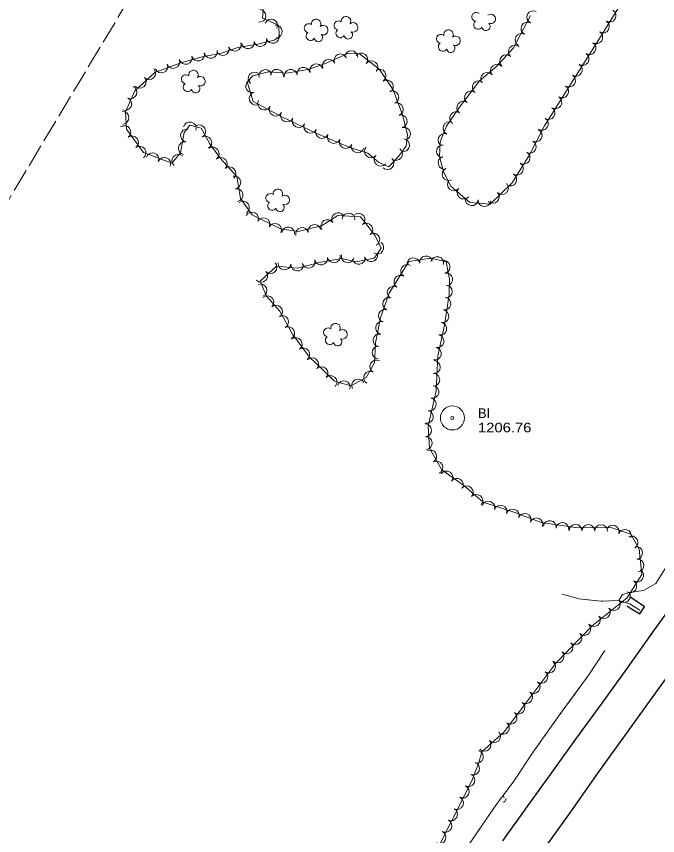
# Model space of a CAD drawing. Extents: x 298761 to 300931, y 48584 to 50968.
# Drawn here: x 299612 to 300012, y 49634 to 50145 of the extents above; entities that cross this region are included whole.
import ezdxf

# ---------------------------------------------------------------- set-up
doc = ezdxf.new("R2010")
doc.units = 0
doc.header["$LTSCALE"] = 2.4
doc.linetypes.add('LONG_DASHED', pattern=[7.5, 6, -1.5])
for name, color, linetype, lineweight in [('11', 7, 'Continuous', 25), ('15', 7, 'Continuous', 13), ('18', 7, 'Continuous', 13), ('19', 7, 'Continuous', 13), ('4', 7, 'Continuous', 13), ('6', 7, 'Continuous', 13)]:
    doc.layers.add(name, color=color, linetype=linetype, lineweight=lineweight)

msp = doc.modelspace()

# ---------------------------------------------------------------- linework, layer by layer
at = {"layer": '11'}
for points in [[(299915.873, 49630.321), (299931.973, 49652.924), (299946.639, 49673.137), (299961.48, 49693.774), (299977.848, 49716.32), (299993.395, 49737.881), (300010.454, 49762.179), (300027.109, 49784.923), (300040.39, 49803.549), (300059.076, 49829.713), (300075.951, 49853.169), (300090.619, 49873.467), (300108.059, 49897.84), (300124.331, 49920.482), (300138.8, 49940.607), (300155.789, 49964.508), (300172.496, 49987.622), (300191.823, 50014.425), (300209.423, 50038.876), (300227.388, 50064), (300243.582, 50086.409), (300257.176, 50105.425), (300269.259, 50122.088)], [(299941.753, 49625.456), (299958.193, 49648.483), (299975.851, 49673.327), (299990.952, 49694.469), (300010.158, 49721.046), (300026.858, 49744.237), (300044.29, 49768.502), (300061.337, 49792.04), (300080.812, 49818.961), (300101.569, 49847.571), (300120.862, 49874.589), (300136.668, 49896.558), (300155.344, 49923.099), (300176.493, 49952.718), (300194.769, 49978.148), (300214.8, 50006.036), (300236.015, 50035.498), (300257.333, 50065.558), (300273.546, 50088.222), (300287.176, 50107.164)]]:
    msp.add_lwpolyline(points, dxfattribs=at)
at = {"layer": '15', "lineweight": 25}
msp.add_lwpolyline([(299993.22, 49777.093), (299995.217, 49775.769), (300001.302, 49772.039), (300004.276, 49776.384), (299998.285, 49780.558), (299995.294, 49782.557)], dxfattribs=at)
at = {"layer": '15'}
msp.add_arc((299915.879, 49656.261), 1.814, 267.88039, 14.11996, dxfattribs=at)
at = {"layer": '18'}
for points in [[(299933.049, 50145.973), (299922.588, 50125.718), (299912.11, 50114.179), (299901.213, 50105.093), (299888.085, 50087.85), (299880.698, 50076.691), (299876.582, 50066.912), (299876.181, 50057.745), (299878.849, 50048.238), (299883.29, 50039.31), (299895.277, 50029.09), (299907.913, 50028.131), (299921.747, 50041.406), (299932.377, 50058.937), (299941.814, 50076.925), (299960.207, 50106.094), (299976.815, 50132.544), (299999.456, 50169.437)], [(299876.275, 49627.887), (299891.116, 49656.997), (299896.966, 49668.752), (299900.82, 49679.139), (299902.684, 49685.849), (299916.63, 49698.459), (299933.285, 49720.361), (299948.899, 49741.267), (299971.578, 49764.647), (299984.015, 49774.503), (299993.254, 49781.947), (300002.651, 49796.774), (300000.918, 49812.588), (299995.831, 49821.813), (299983.919, 49825.836), (299961.184, 49826.042), (299939.705, 49829.183), (299923.913, 49835.134), (299903.509, 49841.801), (299891.565, 49852.222), (299877.646, 49861.998), (299869.95, 49875.684), (299869.244, 49889.438), (299874.196, 49911.402), (299875.17, 49933.356), (299879.366, 49952.538), (299882.29, 49971.577), (299882.575, 49981.193), (299880.385, 49992.018), (299870.949, 49994.324), (299857.19, 49992.154), (299844.909, 49972.449), (299839.431, 49957.01), (299836.315, 49941.374), (299835.746, 49929.004), (299830.565, 49919.818), (299820.828, 49914.584), (299810.698, 49917.533), (299802.151, 49925.827), (299795.085, 49932.492), (299784.539, 49946.75), (299776.599, 49961.272), (299768.268, 49970.524), (299764.357, 49979.899), (299774.434, 49989.353), (299787.655, 49988.159), (299802.096, 49991.862), (299815.183, 49994.133), (299824.307, 49991.981), (299835.486, 49994.317), (299839.757, 50000.568), (299836.109, 50008.351), (299830.568, 50015.668), (299826.963, 50020.166), (299812.741, 50021.043), (299802.558, 50014.574), (299788.088, 50010.998), (299777.048, 50012.592), (299759.232, 50021.403), (299751.972, 50031.678), (299749.613, 50045.385), (299739.553, 50056.478), (299732.832, 50065.661), (299727.505, 50075.492), (299720.386, 50077.486), (299716.719, 50072.761), (299714.489, 50060.051), (299709.158, 50053.718), (299691.46, 50060.346), (299680.801, 50074.84), (299680.15, 50085.825), (299685.979, 50098.782), (299698.448, 50110.252), (299714.75, 50116.42), (299728.009, 50120.006), (299740.145, 50122.434), (299750.282, 50126.002), (299762.861, 50128.024), (299772.978, 50130.55), (299776.438, 50132.498), (299775.707, 50139.951), (299765.739, 50144.23), (299766.764, 50155.882)]]:
    msp.add_lwpolyline(points, dxfattribs=at)
msp.add_lwpolyline([(299847.305, 50099.383), (299838.874, 50112.086), (299831.645, 50117.807), (299826.357, 50121.902), (299818.74, 50122.079), (299812.492, 50119.322), (299804.54, 50115.619), (299794.093, 50112.158), (299780.681, 50109.864), (299769.487, 50110.804), (299759.586, 50108.305), (299756.232, 50104.469), (299759.795, 50092.252), (299777.882, 50082.645), (299799.618, 50072.247), (299820.276, 50063.532), (299831.5, 50059.942), (299838.32, 50054.077), (299844.523, 50051.411), (299850.415, 50057.694), (299855.549, 50064.338), (299856.369, 50071.605), (299853.147, 50083.876)], close=True, dxfattribs=at)
for centre, radius, start, end in [((299763.766, 50145.667), 3.995, 264.98042, 84.9651), ((299934.844, 50144.892), 3.995, 62.69289, 242.67757), ((299982.54, 50145.87), 3.995, 238.47049, 58.45516), ((299771.099, 50139.653), 3.995, 336.77509, 156.75977), ((299799.268, 50140.673), 2.974, 328.01895, 189.25284), ((299817.879, 50142.36), 2.974, 328.01895, 189.25284), ((299899.23, 50145.045), 2.777, 50.98984, 258.76284), ((299908.298, 50143.803), 2.975, 245.66977, 128.64304), ((299774.004, 50135.893), 3.995, 275.60939, 95.59407), ((299794.585, 50138.037), 2.777, 50.98984, 258.76284), ((299803.653, 50136.795), 2.975, 245.66977, 128.64304), ((299813.196, 50139.724), 2.777, 50.98984, 258.76284), ((299822.264, 50138.482), 2.975, 245.66977, 128.64304), ((299900.39, 50140.119), 2.783, 127.66686, 328.6779), ((299905.336, 50139.142), 2.611, 190.375, 48.30761), ((299931.178, 50137.794), 3.995, 62.69289, 242.67757), ((299978.361, 50139.061), 3.995, 238.47049, 58.45516), ((299772.081, 50132.481), 3.995, 194.02658, 14.01126), ((299795.745, 50133.111), 2.783, 127.66686, 328.6779), ((299800.691, 50132.134), 2.611, 190.375, 48.30761), ((299814.356, 50134.798), 2.783, 127.66686, 328.6779), ((299819.302, 50133.821), 2.611, 190.375, 48.30761), ((299877.177, 50131.349), 2.777, 50.98984, 258.76284), ((299881.86, 50133.985), 2.974, 328.01895, 189.25284), ((299886.245, 50130.107), 2.975, 245.66977, 128.64304), ((299927.512, 50130.695), 3.995, 62.69289, 242.67757), ((299974.179, 50132.279), 3.995, 237.88288, 57.86756), ((299748.454, 50127.575), 3.995, 199.3986, 19.38328), ((299756.651, 50129.144), 3.995, 189.1395, 9.12418), ((299764.33, 50130.546), 3.995, 194.02658, 14.01126), ((299878.337, 50126.423), 2.783, 127.66686, 328.6779), ((299969.931, 50125.513), 3.995, 237.88288, 57.86756), ((299733.426, 50123.222), 3.995, 191.32122, 11.3059), ((299740.918, 50124.923), 3.995, 199.3986, 19.38328), ((299821.14, 50119.91), 4.036, 358.67649, 178.66117), ((299883.283, 50125.446), 2.611, 190.375, 48.30761), ((299923.257, 50123.344), 3.995, 47.76661, 227.75129), ((299709.998, 50116.858), 3.995, 200.73222, 20.7169), ((299717.775, 50119.404), 3.995, 195.14168, 15.12636), ((299725.488, 50121.49), 3.995, 195.14168, 15.12636), ((299807.162, 50114.509), 4.036, 24.9776, 204.96228), ((299814.45, 50117.877), 4.036, 23.81767, 203.80235), ((299827.358, 50118.455), 4.036, 322.25364, 142.23832), ((299917.886, 50117.43), 3.995, 47.76661, 227.75129), ((299965.683, 50118.747), 3.995, 237.88288, 57.86756), ((299694.944, 50109.869), 3.995, 222.61803, 42.60271), ((299702.526, 50114.031), 3.995, 200.73222, 20.7169), ((299791.266, 50109.531), 4.036, 9.71366, 189.69834), ((299799.354, 50111.675), 4.036, 18.33724, 198.32192), ((299833.695, 50113.491), 4.036, 321.64972, 141.6344), ((299912.144, 50111.485), 3.995, 39.82926, 219.81394), ((299961.434, 50111.981), 3.995, 237.88288, 57.86756), ((299717.87, 50106.128), 2.777, 50.98984, 258.76284), ((299722.553, 50108.764), 2.974, 328.01895, 189.25284), ((299726.938, 50104.886), 2.975, 245.66977, 128.64304), ((299760.871, 50106.565), 4.036, 48.84289, 228.82757), ((299767.479, 50108.118), 4.036, 14.17319, 194.15786), ((299774.759, 50108.241), 4.036, 355.20759, 175.19227), ((299783.31, 50108.17), 4.036, 9.71366, 189.69834), ((299838.849, 50108.303), 4.036, 303.57995, 123.56463), ((299906.008, 50106.368), 3.995, 39.82926, 219.81394), ((299957.184, 50105.221), 3.995, 237.7735, 57.75818), ((299689.064, 50104.461), 3.995, 222.61803, 42.60271), ((299719.03, 50101.202), 2.783, 127.66686, 328.6779), ((299759.223, 50101.758), 4.036, 106.26661, 286.25128), ((299843.313, 50101.578), 4.036, 303.57995, 123.56463), ((299900.763, 50101.05), 3.995, 52.72374, 232.70842), ((299683.303, 50097.93), 3.995, 245.78598, 65.77066), ((299723.976, 50100.225), 2.611, 190.375, 48.30761), ((299761.483, 50094.009), 4.036, 106.26661, 286.25128), ((299846.751, 50094.862), 4.036, 290.65071, 110.63539), ((299895.923, 50094.693), 3.995, 52.72374, 232.70842), ((299952.923, 50098.463), 3.995, 237.7735, 57.75818), ((299680.025, 50090.645), 3.995, 245.78598, 65.77066), ((299766.842, 50090.901), 4.036, 152.03243, 332.01711), ((299891.083, 50088.336), 3.995, 52.72374, 232.70842), ((299948.662, 50091.705), 3.995, 237.7735, 57.75818), ((299773.97, 50087.115), 4.036, 152.03243, 332.01711), ((299849.596, 50087.309), 4.036, 290.65071, 110.63539), ((299944.4, 50084.947), 3.995, 237.7735, 57.75818), ((299678.278, 50082.063), 3.995, 273.39919, 93.38387), ((299781.067, 50083.463), 4.036, 154.44229, 334.42696), ((299852.02, 50079.85), 4.036, 284.71973, 104.70441), ((299886.635, 50081.871), 3.995, 56.50402, 236.4887), ((299679.49, 50073.094), 3.995, 306.33871, 126.32339), ((299720.295, 50075.34), 3.995, 344.36034, 164.34502), ((299726.184, 50073.54), 3.995, 298.45904, 118.44372), ((299788.348, 50079.98), 4.036, 154.44229, 334.42696), ((299795.629, 50076.497), 4.036, 154.44229, 334.42696), ((299882.473, 50075.518), 3.995, 67.18134, 247.16602), ((299940.139, 50078.189), 3.995, 237.7735, 57.75818), ((299718.516, 50070.905), 3.995, 80.05627, 260.04094), ((299802.871, 50073.167), 4.036, 157.13422, 337.11889), ((299854.07, 50072.044), 4.036, 284.71973, 104.70441), ((299879.374, 50068.154), 3.995, 67.18134, 247.16602), ((299936.332, 50070.977), 3.995, 242.32492, 62.3096), ((299684.223, 50066.657), 3.995, 306.33871, 126.32339), ((299717.136, 50063.036), 3.995, 80.05627, 260.04094), ((299729.991, 50066.516), 3.995, 298.45904, 118.44372), ((299810.308, 50070.03), 4.036, 157.13422, 337.11889), ((299817.745, 50066.893), 4.036, 157.13422, 337.11889), ((299853.478, 50064.823), 4.036, 263.5697, 83.55438), ((299932.621, 50063.903), 3.995, 242.32492, 62.3096), ((299688.956, 50060.221), 3.995, 306.33871, 126.32339), ((299734.62, 50059.678), 3.995, 306.20791, 126.19258), ((299825.142, 50064.194), 4.036, 162.27077, 342.25545), ((299833.423, 50061.074), 4.036, 139.3131, 319.29778), ((299849.095, 50059.44), 4.036, 232.31342, 52.2981), ((299878.419, 50061.065), 3.995, 87.50292, 267.4876), ((299696.913, 50056.071), 3.995, 339.47646, 159.46113), ((299704.395, 50053.269), 3.995, 339.47646, 159.46113), ((299713.132, 50055.192), 3.995, 49.91762, 229.9023), ((299739.679, 50053.226), 3.995, 312.21186, 132.19654), ((299839.543, 50055.811), 4.036, 139.3131, 319.29778), ((299843.746, 50053.671), 4.036, 226.84708, 46.83176), ((299879.43, 50053.906), 3.995, 105.68366, 285.66834), ((299928.785, 50057.047), 3.995, 238.77695, 58.76162), ((299745.046, 50047.308), 3.995, 312.21186, 132.19654), ((299924.643, 50050.215), 3.995, 238.77695, 58.76162), ((299881.919, 50046.761), 3.995, 116.45451, 296.43919), ((299920.501, 50043.384), 3.995, 238.77695, 58.76162), ((299748.145, 50041.584), 3.995, 279.77271, 99.75739), ((299885.185, 50040.442), 3.995, 139.55707, 319.54175), ((299749.5, 50033.711), 3.995, 279.77271, 99.75739), ((299775.288, 50034.526), 2.974, 328.01895, 189.25284), ((299891.264, 50035.259), 3.995, 139.55707, 319.54175), ((299915.289, 50038.107), 3.995, 223.82636, 43.81104), ((299770.605, 50031.89), 2.777, 50.98984, 258.76284), ((299779.673, 50030.648), 2.975, 245.66977, 128.64304), ((299896.366, 50031.104), 3.995, 175.66756, 355.65224), ((299904.332, 50030.5), 3.995, 175.66756, 355.65224), ((299909.524, 50032.575), 3.995, 223.82636, 43.81104), ((299753.477, 50025.925), 3.995, 305.25152, 125.23619), ((299771.765, 50026.964), 2.783, 127.66686, 328.6779), ((299776.711, 50025.987), 2.611, 190.375, 48.30761), ((299759.179, 50019.097), 3.995, 333.69271, 153.67739), ((299812.934, 50018.688), 3.995, 32.43441, 212.41909), ((299819.488, 50018.532), 3.995, 356.47898, 176.46366), ((299825.725, 50018.367), 3.995, 308.7187, 128.70337), ((299766.34, 50015.555), 3.995, 333.69271, 153.67739), ((299773.501, 50012.013), 3.995, 333.69271, 153.67739), ((299798.191, 50011.341), 3.995, 13.88914, 193.87382), ((299806.19, 50014.404), 3.995, 32.43441, 212.41909), ((299830.624, 50012.13), 3.995, 307.14349, 127.12817), ((299781.764, 50009.798), 3.995, 351.79184, 171.77652), ((299790.436, 50009.424), 3.995, 13.88914, 193.87382), ((299834.922, 50005.956), 3.995, 295.1208, 115.10548), ((299837.433, 50000.873), 3.995, 235.66479, 55.64947), ((299810.244, 49995.398), 3.995, 189.85222, 9.8369), ((299818.913, 49995.402), 3.995, 166.73634, 346.72102), ((299825.792, 49994.427), 3.995, 191.81054, 11.79521), ((299833.612, 49996.062), 3.995, 191.81054, 11.79521), ((299867.836, 49991.716), 3.995, 8.97024, 188.95492), ((299874.832, 49991.223), 3.995, 346.2747, 166.25938), ((299770.72, 49988.736), 3.995, 223.18066, 43.16534), ((299779.461, 49990.998), 3.995, 174.84723, 354.83191), ((299787.418, 49990.28), 3.995, 174.84723, 354.83191), ((299794.461, 49992.063), 3.995, 194.38972, 14.3744), ((299802.372, 49994.032), 3.995, 189.85222, 9.8369), ((299856.039, 49986.355), 3.995, 58.07473, 238.05941), ((299859.945, 49990.472), 3.995, 8.97024, 188.95492), ((299878.888, 49988.875), 3.995, 281.44477, 101.42945), ((299764.894, 49983.27), 3.995, 223.18066, 43.16534), ((299880.472, 49981.044), 3.995, 281.44477, 101.42945), ((299851.814, 49979.574), 3.995, 58.07473, 238.05941), ((299764.464, 49974.21), 3.995, 292.65226, 112.63694), ((299847.588, 49972.794), 3.995, 58.07473, 238.05941), ((299880.256, 49973.54), 3.995, 268.31002, 88.2947), ((299768.804, 49966.804), 3.995, 312.00924, 131.99392), ((299844.78, 49965.832), 3.995, 70.47217, 250.45685), ((299879.299, 49965.878), 3.995, 261.27643, 81.2611), ((299774.15, 49960.867), 3.995, 312.00924, 131.99392), ((299842.108, 49958.303), 3.995, 70.47217, 250.45685), ((299878.086, 49957.981), 3.995, 261.27643, 81.2611), ((299777.955, 49954.433), 3.995, 298.67559, 118.66027), ((299840.333, 49950.839), 3.995, 78.7372, 258.72188), ((299876.724, 49950.246), 3.995, 257.66875, 77.65343), ((299781.788, 49947.423), 3.995, 298.67559, 118.66027), ((299806.606, 49947.951), 2.777, 50.98984, 258.76284), ((299811.289, 49950.587), 2.974, 328.01895, 189.25284), ((299815.674, 49946.709), 2.975, 245.66977, 128.64304), ((299786.473, 49940.62), 3.995, 306.49633, 126.481), ((299807.766, 49943.025), 2.783, 127.66686, 328.6779), ((299812.712, 49942.048), 2.611, 190.375, 48.30761), ((299838.772, 49943.004), 3.995, 78.7372, 258.72188), ((299875.017, 49942.442), 3.995, 257.66875, 77.65343), ((299838.132, 49935.374), 3.995, 87.37401, 267.35868), ((299873.31, 49934.637), 3.995, 257.66875, 77.65343), ((299791.223, 49934.196), 3.995, 306.49633, 126.481), ((299796.795, 49928.005), 3.995, 316.68045, 136.66513), ((299836.822, 49926.656), 3.995, 60.58421, 240.56889), ((299872.765, 49926.32), 3.995, 267.46737, 87.45205), ((299802.56, 49922.517), 3.995, 315.86834, 135.85302), ((299832.897, 49919.697), 3.995, 60.58421, 240.56889), ((299808.293, 49916.953), 3.995, 315.86834, 135.85302), ((299825.434, 49914.686), 3.995, 28.26735, 208.25203), ((299872.411, 49918.339), 3.995, 267.46737, 87.45205), ((299816.515, 49913.662), 3.995, 343.77656, 163.76124), ((299871.906, 49910.752), 3.995, 257.3022, 77.28688), ((299870.149, 49902.958), 3.995, 257.3022, 77.28688), ((299868.392, 49895.164), 3.995, 257.3022, 77.28688), ((299867.289, 49886.744), 3.995, 272.94611, 92.93078), ((299867.698, 49878.765), 3.995, 272.94611, 92.93078), ((299870.479, 49870.478), 3.995, 299.35786, 119.34254), ((299874.394, 49863.514), 3.995, 299.35786, 119.34254), ((299880.596, 49857.371), 3.995, 324.9254, 144.91008), ((299887.134, 49852.779), 3.995, 324.9254, 144.91008), ((299893.237, 49847.988), 3.995, 318.90334, 138.88802), ((299899.257, 49842.736), 3.995, 318.90334, 138.88802), ((299906.824, 49838.518), 3.995, 341.91287, 161.89755), ((299914.418, 49836.037), 3.995, 341.91287, 161.89755), ((299922.012, 49833.555), 3.995, 341.91287, 161.89755), ((299929.42, 49830.824), 3.995, 339.35943, 159.34411), ((299936.896, 49828.007), 3.995, 339.35943, 159.34411), ((299945.117, 49826.278), 3.995, 351.68794, 171.67261), ((299953.022, 49825.122), 3.995, 351.68794, 171.67261), ((299961.211, 49823.951), 3.995, 359.48852, 179.4732), ((299969.2, 49823.878), 3.995, 359.48852, 179.4732), ((299977.189, 49823.806), 3.995, 359.48852, 179.4732), ((299984.461, 49823.446), 3.995, 341.34646, 161.33114), ((299992.03, 49820.89), 3.995, 341.34646, 161.33114), ((299996.261, 49816.702), 3.995, 298.8816, 118.86628), ((299999.072, 49810.235), 3.995, 276.26155, 96.24623), ((299999.943, 49802.293), 3.995, 276.26155, 96.24623), ((299999.703, 49796.029), 3.995, 237.64211, 57.62679), ((299995.426, 49789.281), 3.995, 237.64211, 57.62679), ((299991.45, 49783.179), 3.995, 218.86657, 38.85125), ((299985.229, 49778.166), 3.995, 218.86657, 38.85125), ((299978.997, 49773.194), 3.995, 218.40357, 38.38825), ((299972.735, 49768.232), 3.995, 218.40357, 38.38825), ((299966.696, 49762.618), 3.995, 225.87961, 45.86429), ((299961.134, 49756.883), 3.995, 225.87961, 45.86429), ((299955.571, 49751.149), 3.995, 225.87961, 45.86429), ((299950.009, 49745.414), 3.995, 225.87961, 45.86429), ((299944.687, 49739.121), 3.995, 233.25282, 53.2375), ((299939.906, 49732.72), 3.995, 233.25282, 53.2375), ((299935.125, 49726.319), 3.995, 233.25282, 53.2375), ((299930.341, 49719.944), 3.995, 232.75711, 52.74179), ((299925.505, 49713.584), 3.995, 232.75711, 52.74179), ((299920.669, 49707.225), 3.995, 232.75711, 52.74179), ((299915.833, 49700.865), 3.995, 232.75711, 52.74179), ((299910.365, 49695.613), 3.995, 222.12761, 42.11229), ((299904.439, 49690.255), 3.995, 222.12761, 42.11229), ((299899.67, 49682.812), 3.995, 254.48267, 74.46735), ((299897.204, 49675.406), 3.995, 249.65076, 69.63543), ((299894.351, 49668.19), 3.995, 243.54994, 63.53462), ((299890.791, 49661.038), 3.995, 243.54994, 63.53462), ((299887.202, 49653.923), 3.995, 242.99405, 62.97872), ((299883.573, 49646.805), 3.995, 242.99405, 62.97872), ((299879.944, 49639.688), 3.995, 242.99405, 62.97872), ((299876.316, 49632.57), 3.995, 242.99405, 62.97872)]:
    msp.add_arc(centre, radius, start, end, dxfattribs=at)
at = {"layer": '19'}
for p, q in [((299974.489, 49780.266), (299973.236, 49780.413)), ((299978.256, 49780.024), (299976.996, 49779.978)), ((299982.035, 49780.16), (299980.775, 49780.115)), ((299946.912, 49702.834), (299948.524, 49705.081)), ((299942.076, 49696.094), (299943.688, 49698.341))]:
    msp.add_line(p, q, dxfattribs=at)
for points in [[(299988.275, 49780.386), (299990.631, 49784.132), (299995.227, 49785.511), (300003.713, 49786.579), (300011.41, 49791.155), (300021.077, 49806.65)], [(299988.275, 49780.386), (299990.631, 49784.132), (299995.227, 49785.511), (300003.713, 49786.579), (300011.41, 49791.155), (300011.501, 49791.301)], [(300001.373, 49774.354), (299995.158, 49778.315), (299988.275, 49780.386), (299976.962, 49779.977), (299963.549, 49781.547), (299952.88, 49784.399)], [(299970.729, 49780.707), (299963.549, 49781.547), (299952.88, 49784.399)], [(300001.373, 49774.354), (299995.158, 49778.315), (299988.275, 49780.386), (299984.554, 49780.251)], [(299916.065, 49658.7), (299922.743, 49667.517), (299934.961, 49686.177), (299952.964, 49711.269), (299969.572, 49733.924), (299979.52, 49749.124)], [(299956.632, 49716.272), (299969.572, 49733.924), (299979.52, 49749.124)], [(299951.748, 49709.574), (299952.964, 49711.269), (299953.365, 49711.816)], [(299916.065, 49658.7), (299922.743, 49667.517), (299934.961, 49686.177), (299938.853, 49691.601)], [(299641.013, 49277.236), (299655.996, 49298.597), (299676.723, 49327.019), (299694.754, 49354.227), (299711.353, 49379.743), (299726.367, 49400.675), (299742.833, 49421.582), (299758.372, 49439.726), (299776.025, 49462.976), (299791.796, 49485.973), (299804.246, 49502.71), (299816.164, 49518.187), (299830.285, 49536.354), (299842.906, 49554.758), (299856.263, 49574.089), (299873.188, 49597.501), (299888.265, 49618.536), (299902.498, 49639.532), (299910.218, 49650.751), (299915.014, 49657.354), (299916.065, 49658.7), (299916.722, 49657.092)], [(299900.644, 49636.797), (299902.498, 49639.532), (299910.218, 49650.751), (299915.014, 49657.354), (299916.065, 49658.7), (299916.722, 49657.092)]]:
    msp.add_lwpolyline(points, dxfattribs=at)
at = {"layer": '4', "linetype": 'LONG_DASHED'}
msp.add_line((299332.839, 49573.576), (299872.076, 50472.442), dxfattribs=at)
at = {"layer": '6'}
for radius in [7.5, 0.96]:
    msp.add_circle((299884.324, 49894.484), radius, dxfattribs=at)

# ---------------------------------------------------------------- texts
msp.add_text('BI', height=6, dxfattribs=at).set_placement((299900.324, 49894.484))
at = {"layer": '6', "width": 1.15}
msp.add_text('1206.76', height=6, dxfattribs=at).set_placement((299900.324, 49885.484))

doc.saveas('drawing.dxf')
